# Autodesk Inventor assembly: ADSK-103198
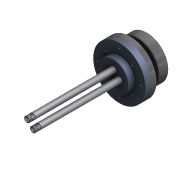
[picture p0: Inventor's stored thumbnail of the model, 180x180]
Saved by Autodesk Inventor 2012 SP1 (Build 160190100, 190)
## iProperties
Shininess: 0.0
Created: 2001-01
Part Number: ADSK-103198
Document SubType Name: Assembly
Designer: gao
Stock Number: ADSK-103198
Density: 0.0
Volumn: 0.0
Area: 0.0
PropertySet Name: Model Information
Control State: 0
Master: False
Checked Out: False
Author: gao
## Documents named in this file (4)
- D:\AOTC\Autodesk Inventor 2012 Essential for New Users\Autodesk Inventor 2012 Essentials - Project Files\Learning\Workspace\Sub-Assemblies\ADSK-103198.iam
- D:\AOTC\Autodesk Inventor 2012 Essential for New Users\Autodesk Inventor 2012 Essentials - Project Files\Learning\Workspace\Parts\ADSK-104063.ipt
- D:\AOTC\Autodesk Inventor 2012 Essential for New Users\Autodesk Inventor 2012 Essentials - Project Files\Learning\Workspace\Parts\ADSK-103916.ipt
- D:\AOTC\Autodesk Inventor 2012 Essential for New Users\Autodesk Inventor 2012 Essentials - Project Files\Learning\Workspace\Parts\ADSK-103379.ipt
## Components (6 placed, 3 different names)
1. ADSK-103916:1 — Insert:1, Insert:2, Insert:3, Insert:4, Insert:5, Mate:1
2. ADSK-104063:1 — Insert:1
3. ADSK-104063:2 — Insert:2
4. ADSK-104063:3 — Insert:3
5. ADSK-104063:4 — Insert:4
6. ADSK-103379:1 — Insert:5, Mate:1
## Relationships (6: Insert 5, Mate 1)
- Insert:1: ADSK-103916:1 ↔ ADSK-104063:1
- Insert:2: ADSK-103916:1 ↔ ADSK-104063:2
- Insert:3: ADSK-103916:1 ↔ ADSK-104063:3
- Insert:4: ADSK-103916:1 ↔ ADSK-104063:4
- Insert:5: ADSK-103916:1 ↔ ADSK-103379:1
- Mate:1: ADSK-103916:1 ↔ ADSK-103379:1
